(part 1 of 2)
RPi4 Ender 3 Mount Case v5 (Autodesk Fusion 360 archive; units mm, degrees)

design "RPi4 Ender 3 Mount Case" references "RPi_4_dummy_v2"
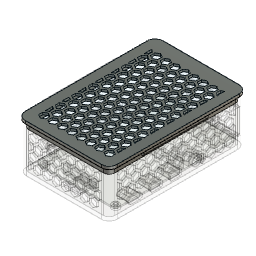
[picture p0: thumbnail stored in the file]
parameter "inner_width" = 60
parameter "inner_length" = 92
parameter "inner_height" = 30
parameter "wall_thickness" = 1.5
parameter "tolerance" = 0.2
parameter "cover_height" = 2
sketch "Sketch1" plane through (0, 0, 0) normal (0, 0, 1) x axis (1, 0, 0)
  line L1 (60, 0) -> (0, 0)
  line L2 (60, -92) -> (60, 0)
  line L3 (0, -92) -> (60, -92)
  line L4 (0, 0) -> (0, -92)
  point P1 (0, 0)
  point P2 (0, 0)
  point P3 (60, 0)
  point P5 (0, -92)
  horizontal L1
  vertical L2
  horizontal L3
  vertical L4
  coincident P1 P2
  dimension "d6" distance P2 P3 = 60 (= "inner_width")
  dimension "d7" distance P2 P5 = 92 (= "inner_length")
extrude "Extrude1" new body sketch "Sketch1" along normal blind 30 (= "inner_height")
fillet "Fillet1" radius 4
shell "Shell1" outerThickness 1.5 (= "wall_thickness")
sketch "Sketch2" plane through (0, 0, 0) normal (1, 0, 0) x axis (0, 1, 0)
  line L1 (-4, 30) -> (-4, 0)
  line L2 (-88, 30) -> (-4, 30)
  line L3 (-88, 0) -> (-88, 30)
  line L4 (-4, 0) -> (-88, 0)
  line L5 (-23, 28.5) -> (-69, 28.5)
  line L6 (-23, 26.25) -> (-23, 28.5)
  line L7 (-69, 26.25) -> (-23, 26.25)
  line L8 (-69, 28.5) -> (-69, 26.25)
  line L9 (-46, 30) -> (-46, 28.5)
  point P10 (-46, 28.5)
  point P11 (-46, 30)
  point P8 (-23, 26.25)
  point P9 (-69, 26.25)
  point P6 (-69, 28.5)
  horizontal L5
  vertical L6
  horizontal L7
  vertical L8
  midpoint L5 P10
  perpendicular L5 L9
  midpoint L2 P11
  dimension "d32" distance P8 P9 = 46 (= "inner_length / 2")
  dimension "d33" distance P6 P9 = 2.25 (= "wall_thickness * 1.5")
  dimension "d34" distance P10 P11 = 1.5 (= "wall_thickness")
extrude "Extrude2" cut sketch "Sketch2" profile of L5 L6 L7 L8 no distance stored taper -45
work_plane "WorkPlane1"
mirror "Mirror1" mirrorStitchTolerance 0.1
sketch "Sketch1" plane through (0, 0, 30) normal (0, 0, 1) x axis (-1, 0, 0)
  line L1 (-56, 0) -> (-4, 0)
  line L2 (-60, 88) -> (-60, 4)
  line L3 (-4, 92) -> (-56, 92)
  line L4 (0, 4) -> (0, 88)
  line L5 (-61.5, 4) -> (-61.5, 88)
  line L6 (-4, -1.5) -> (-56, -1.5)
  line L7 (1.5, 88) -> (1.5, 4)
  line L8 (-56, 93.5) -> (-4, 93.5)
  arc A1 centre (-4, 4) radius 4 clockwise from (0, 4) to (-4, 0)
  arc A2 centre (-56, 4) radius 4 clockwise from (-56, 0) to (-60, 4)
  arc A3 centre (-56, 88) radius 4 clockwise from (-60, 88) to (-56, 92)
  arc A4 centre (-4, 88) radius 4 clockwise from (-4, 92) to (0, 88)
  arc A5 centre (-56, 88) radius 5.5 clockwise from (-61.5, 88) to (-56, 93.5)
  arc A6 centre (-56, 4) radius 5.5 clockwise from (-56, -1.5) to (-61.5, 4)
  arc A7 centre (-4, 4) radius 5.5 clockwise from (1.5, 4) to (-4, -1.5)
  arc A8 centre (-4, 88) radius 5.5 clockwise from (-4, 93.5) to (1.5, 88)
extrude "Extrude1" new body sketch "Sketch1" along normal blind 2 (= "cover_height")
sketch "Sketch2" plane through (0, 0, 30) normal (0, 0, -1) x axis (1, 0, 0)
  line L1 (4, 93.5) -> (56, 93.5)
  line L2 (-1.5, 4) -> (-1.5, 88)
  line L3 (56, -1.5) -> (4, -1.5)
  line L4 (61.5, 88) -> (61.5, 4)
  line L5 (4, 91.8) -> (56, 91.8)
  line L6 (0.2, 4) -> (0.2, 88)
  line L7 (56, 0.2) -> (4, 0.2)
  line L8 (59.8, 88) -> (59.8, 4)
  arc A1 centre (4, 88) radius 5.5 clockwise from (-1.5, 88) to (4, 93.5)
  arc A2 centre (4, 4) radius 5.5 clockwise from (4, -1.5) to (-1.5, 4)
  arc A3 centre (56, 4) radius 5.5 clockwise from (61.5, 4) to (56, -1.5)
  arc A4 centre (56, 88) radius 5.5 clockwise from (56, 93.5) to (61.5, 88)
  arc A5 centre (4, 88) radius 3.8 clockwise from (0.2, 88) to (4, 91.8)
  arc A6 centre (4, 4) radius 3.8 clockwise from (4, 0.2) to (0.2, 4)
  arc A7 centre (56, 4) radius 3.8 clockwise from (59.8, 4) to (56, 0.2)
  arc A8 centre (56, 88) radius 3.8 clockwise from (56, 91.8) to (59.8, 88)
extrude "Extrude2" add sketch "Sketch2" profile of A8 L8 A7 A6 L6 L7 A5 L5 along normal blind 4.5 (= "wall_thickness * 3")
shell "Shell1" innerThickness 1.5 (= "wall_thickness")
sketch "Sketch3" plane through (0.2, 0, 0) normal (-1, 0, 0) x axis (0, -1, 0)
  line L1 (4, 30) -> (88, 30)
  line L2 (4, 25.5) -> (4, 30)
  line L3 (88, 25.5) -> (4, 25.5)
  line L4 (88, 30) -> (88, 25.5)
  line L5 (69, 26.25) -> (23, 26.25)
  line L6 (69, 28.5) -> (69, 26.25)
  line L7 (23, 26.25) -> (23, 28.5)
  line L8 (23, 28.5) -> (69, 28.5)
extrude "Extrude3" add sketch "Sketch3" profile of L5 L6 L7 L8 along normal blind 1.5 (= "wall_thickness") taper -45
mirror "Mirror1" mirrorStitchTolerance 0.1
offset_faces "OffsetFaces1" distance 0.5
chamfer "Chamfer1" distance 0.5
external_derived "ExternalDerived1" sketch "Sketch3" bodies "Body1", "Body2", "Power USB C", "Micro HDMI 2", "3.5 mm Audio", "Micro HDMI 1", "USB 2.0", "Display"
position "Position1"
sketch "Sketch1" plane through (0, 0, 0) normal (0, 0, 1) x axis (-1, 0, 0)
  line L1 (-60, 4) -> (-60, 88)
  line L2 (-4, 0) -> (-56, 0)
  line L3 (0, 88) -> (0, 4)
  line L4 (-56, 92) -> (-4, 92)
  arc A1 centre (-56, 88) radius 4 clockwise from (-60, 88) to (-56, 92)
  arc A2 centre (-56, 4) radius 4 clockwise from (-56, 0) to (-60, 4)
  arc A3 centre (-4, 4) radius 4 clockwise from (0, 4) to (-4, 0)
  arc A4 centre (-4, 88) radius 4 clockwise from (-4, 92) to (0, 88)
  circle C1 centre (-55.5, 24.9993) radius 1.35
  circle C2 centre (-6.5, 24.9993) radius 1.35
  circle C3 centre (-6.5, 82.9993) radius 1.35
  circle C4 centre (-55.5, 82.9993) radius 1.35
extrude "Extrude3" add sketch "Sketch1" profile of C1 C2 C3 C4 to an object
offset_faces "OffsetFaces1" distance 1.2
sketch "Sketch2" plane through (0, 1.5, 0) normal (0, 1, 0) x axis (-1, 0, 0)
  line L1 (-4, 30) -> (-4, -1.5)
  line L2 (-56, 30) -> (-4, 30)
  line L3 (-56, -1.5) -> (-56, 30)
  line L4 (-4, -1.5) -> (-56, -1.5)
  line L5 (-42.65, 3) -> (-57.35, 3)
  line L6 (-42.65, 19.5) -> (-42.65, 3)
  line L7 (-57.35, 19.5) -> (-42.65, 19.5)
  line L8 (-57.35, 3) -> (-57.35, 19.5)
  line L9 (-24.65, 3) -> (-39.35, 3)
  line L10 (-24.65, 19.5) -> (-24.65, 3)
  line L11 (-39.35, 19.5) -> (-24.65, 19.5)
  line L12 (-39.35, 3) -> (-39.35, 19.5)
  line L13 (-5.25, 3) -> (-21.25, 3)
  line L14 (-5.25, 16.5) -> (-5.25, 3)
  line L15 (-21.25, 16.5) -> (-5.25, 16.5)
  line L16 (-21.25, 3) -> (-21.25, 16.5)
  line L17 (-42.15, 2.5) -> (-57.85, 2.5)
  line L18 (-42.15, 20) -> (-42.15, 2.5)
  line L19 (-57.85, 20) -> (-42.15, 20)
  line L20 (-57.85, 2.5) -> (-57.85, 20)
  line L21 (-24.15, 2.5) -> (-39.85, 2.5)
  line L22 (-24.15, 20) -> (-24.15, 2.5)
  line L23 (-39.85, 20) -> (-24.15, 20)
  line L24 (-39.85, 2.5) -> (-39.85, 20)
  line L25 (-4.75, 2.5) -> (-21.75, 2.5)
  line L26 (-4.75, 17) -> (-4.75, 2.5)
  line L27 (-21.75, 17) -> (-4.75, 17)
  line L28 (-21.75, 2.5) -> (-21.75, 17)
  dimension "d44" = 0.5
  dimension "d45" = 0.5 (= "d44")
  dimension "d46" = 0.5 (= "d45")
extrude "Extrude5" cut sketch "Sketch2" profile of L1 L3 L19 L20 L18 L17 L23 L22 L24 L21 L28 L27 L26 L25 against normal blind 3 (magnitude of "-wall_thickness * 2")
sketch "Sketch3" plane through (61.5, 0, 0) normal (1, 0, 0) x axis (0, 1, 0)
  line L1 (-88, -1.5) -> (-88, 30)
  line L2 (-4, -1.5) -> (-88, -1.5)
  line L3 (-4, 30) -> (-4, -1.5)
  line L4 (-88, 30) -> (-4, 30)
  line L5 (-70.7993, 4.7) -> (-70.7993, 4.5)
  line L6 (-78.2993, 6.2) -> (-72.2993, 6.2)
  line L7 (-79.7993, 4.5) -> (-79.7993, 4.7)
  line L8 (-72.2993, 3) -> (-78.2993, 3)
  line L9 (-56.9493, 5.8) -> (-56.9493, 3.5)
  line L10 (-63.5493, 6.3) -> (-57.4493, 6.3)
  line L11 (-64.0493, 3.5) -> (-64.0493, 5.8)
  line L12 (-57.4493, 3) -> (-63.5493, 3)
  line L13 (-43.4493, 5.8) -> (-43.4493, 3.5)
  line L14 (-50.0493, 6.3) -> (-43.9493, 6.3)
  line L15 (-50.5493, 3.5) -> (-50.5493, 5.8)
  line L16 (-43.9493, 3) -> (-50.0493, 3)
  line L17 (-80.2993, 4.5) -> (-80.2993, 4.7)
  line L18 (-72.2993, 2.5) -> (-78.2993, 2.5)
  line L19 (-70.2993, 4.7) -> (-70.2993, 4.5)
  line L20 (-78.2993, 6.7) -> (-72.2993, 6.7)
  line L21 (-64.5493, 3.5) -> (-64.5493, 5.8)
  line L22 (-57.4493, 2.5) -> (-63.5493, 2.5)
  line L23 (-56.4493, 5.8) -> (-56.4493, 3.5)
  line L24 (-63.5493, 6.8) -> (-57.4493, 6.8)
  line L25 (-51.0493, 3.5) -> (-51.0493, 5.8)
  line L26 (-43.9493, 2.5) -> (-50.0493, 2.5)
  line L27 (-42.9493, 5.8) -> (-42.9493, 3.5)
  line L28 (-50.0493, 6.8) -> (-43.9493, 6.8)
  arc A1 centre (-72.2993, 4.5) radius 1.5 clockwise from (-70.7993, 4.5) to (-72.2993, 3)
  arc A2 centre (-72.2993, 4.7) radius 1.5 clockwise from (-72.2993, 6.2) to (-70.7993, 4.7)
  arc A3 centre (-78.2993, 4.7) radius 1.5 clockwise from (-79.7993, 4.7) to (-78.2993, 6.2)
  arc A4 centre (-78.2993, 4.5) radius 1.5 clockwise from (-78.2993, 3) to (-79.7993, 4.5)
  arc A5 centre (-57.4493, 3.5) radius 0.5 clockwise from (-56.9493, 3.5) to (-57.4493, 3)
  arc A6 centre (-57.4493, 5.8) radius 0.5 clockwise from (-57.4493, 6.3) to (-56.9493, 5.8)
  arc A7 centre (-63.5493, 5.8) radius 0.5 clockwise from (-64.0493, 5.8) to (-63.5493, 6.3)
  arc A8 centre (-63.5493, 3.5) radius 0.5 clockwise from (-63.5493, 3) to (-64.0493, 3.5)
  arc A9 centre (-43.9493, 3.5) radius 0.5 clockwise from (-43.4493, 3.5) to (-43.9493, 3)
  arc A10 centre (-43.9493, 5.8) radius 0.5 clockwise from (-43.9493, 6.3) to (-43.4493, 5.8)
  arc A11 centre (-50.0493, 5.8) radius 0.5 clockwise from (-50.5493, 5.8) to (-50.0493, 6.3)
  arc A12 centre (-50.0493, 3.5) radius 0.5 clockwise from (-50.0493, 3) to (-50.5493, 3.5)
  circle C1 centre (-32.4993, 6) radius 3
  arc A13 centre (-78.2993, 4.5) radius 2 clockwise from (-78.2993, 2.5) to (-80.2993, 4.5)
  arc A14 centre (-72.2993, 4.5) radius 2 clockwise from (-70.2993, 4.5) to (-72.2993, 2.5)
  arc A15 centre (-72.2993, 4.7) radius 2 clockwise from (-72.2993, 6.7) to (-70.2993, 4.7)
  arc A16 centre (-78.2993, 4.7) radius 2 clockwise from (-80.2993, 4.7) to (-78.2993, 6.7)
  arc A17 centre (-63.5493, 3.5) radius 1 clockwise from (-63.5493, 2.5) to (-64.5493, 3.5)
  arc A18 centre (-57.4493, 3.5) radius 1 clockwise from (-56.4493, 3.5) to (-57.4493, 2.5)
  arc A19 centre (-57.4493, 5.8) radius 1 clockwise from (-57.4493, 6.8) to (-56.4493, 5.8)
  arc A20 centre (-63.5493, 5.8) radius 1 clockwise from (-64.5493, 5.8) to (-63.5493, 6.8)
  arc A21 centre (-50.0493, 3.5) radius 1 clockwise from (-50.0493, 2.5) to (-51.0493, 3.5)
  arc A22 centre (-43.9493, 3.5) radius 1 clockwise from (-42.9493, 3.5) to (-43.9493, 2.5)
  arc A23 centre (-43.9493, 5.8) radius 1 clockwise from (-43.9493, 6.8) to (-42.9493, 5.8)
  arc A24 centre (-50.0493, 5.8) radius 1 clockwise from (-51.0493, 5.8) to (-50.0493, 6.8)
  circle C2 centre (-32.4993, 6) radius 3.5
  dimension "d49" = 0.5
  dimension "d50" = 0.5
  dimension "d51" = 0.5
  dimension "d52" = 0.5
extrude "Extrude6" cut sketch "Sketch3" profile of A16 L20 A15 L19 L18 A14 A13 L17 L24 A20 A19 L23 L22 A18 A17 L21 L28 A23 A24 L27 L26 A22 A21 L25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 against normal blind 3 (magnitude of "-wall_thickness * 2")
sketch "Sketch5" plane through (61.5, 0, 0) normal (1, 0, 0) x axis (0, 1, 0)
  line L1 (-64.5493, 5.8) -> (-64.5493, 3.5)
  line L2 (-57.4493, 6.8) -> (-63.5493, 6.8)
  line L3 (-56.4493, 3.5) -> (-56.4493, 5.8)
  line L4 (-63.5493, 2.5) -> (-57.4493, 2.5)
  line L5 (-51.0493, 5.8) -> (-51.0493, 3.5)
  line L6 (-43.9493, 6.8) -> (-50.0493, 6.8)
  line L7 (-42.9493, 3.5) -> (-42.9493, 5.8)
  line L8 (-50.0493, 2.5) -> (-43.9493, 2.5)
  line L9 (-80.2993, 4.7) -> (-80.2993, 4.5)
  line L10 (-72.2993, 6.7) -> (-78.2993, 6.7)
  line L11 (-70.2993, 4.5) -> (-70.2993, 4.7)
  line L12 (-78.2993, 2.5) -> (-72.2993, 2.5)
  line L13 (-88, -1.5) -> (-88, 30)
  line L14 (-4, -1.5) -> (-88, -1.5)
  line L15 (-4, 30) -> (-4, -1.5)
  line L16 (-88, 30) -> (-4, 30)
  line L17 (-5.5, 0) -> (-86.5, 0)
  line L18 (-5.5, 28.5) -> (-5.5, 0)
  line L19 (-86.5, 28.5) -> (-5.5, 28.5)
  line L20 (-86.5, 0) -> (-86.5, 28.5)
  line L21 (-72.2993, 8.2) -> (-78.2993, 8.2)
  line L22 (-68.7993, 4.5) -> (-68.7993, 4.7)
  line L23 (-78.2993, 1) -> (-72.2993, 1)
  line L24 (-81.7993, 4.7) -> (-81.7993, 4.5)
  line L25 (-54.9493, 3.5) -> (-54.9493, 5.8)
  line L26 (-57.4493, 8.3) -> (-63.5493, 8.3)
  line L27 (-66.0493, 5.8) -> (-66.0493, 3.5)
  line L28 (-63.5493, 1) -> (-57.4493, 1)
  line L29 (-41.4493, 3.5) -> (-41.4493, 5.8)
  line L30 (-43.9493, 8.3) -> (-50.0493, 8.3)
  line L31 (-52.5493, 5.8) -> (-52.5493, 3.5)
  line L32 (-50.0493, 1) -> (-43.9493, 1)
  line L33 (-87.25, 19.6699) -> (-84.75, 18.2265)
  line L34 (-89.75, 18.2265) -> (-87.25, 19.6699)
  line L35 (-89.75, 15.3397) -> (-89.75, 18.2265)
  line L36 (-87.25, 13.8964) -> (-89.75, 15.3397)
  line L37 (-84.75, 15.3397) -> (-87.25, 13.8964)
  line L38 (-84.75, 18.2265) -> (-84.75, 15.3397)
  line L39 (-84, 25.5) -> (-81.5, 24.0566)
  line L40 (-86.5, 24.0566) -> (-84, 25.5)
  line L41 (-86.5, 21.1699) -> (-86.5, 24.0566)
  line L42 (-84, 19.7265) -> (-86.5, 21.1699)
  line L43 (-81.5, 21.1699) -> (-84, 19.7265)
  line L44 (-81.5, 24.0566) -> (-81.5, 21.1699)
  line L45 (-77.5, 25.5) -> (-75, 24.0566)
  line L46 (-80, 24.0566) -> (-77.5, 25.5)
  line L47 (-80, 21.1699) -> (-80, 24.0566)
  line L48 (-77.5, 19.7265) -> (-80, 21.1699)
  line L49 (-75, 21.1699) -> (-77.5, 19.7265)
  line L50 (-75, 24.0566) -> (-75, 21.1699)
  line L51 (-80.75, 19.6699) -> (-78.25, 18.2265)
  line L52 (-83.25, 18.2265) -> (-80.75, 19.6699)
  line L53 (-83.25, 15.3397) -> (-83.25, 18.2265)
  line L54 (-80.75, 13.8964) -> (-83.25, 15.3397)
  line L55 (-78.25, 18.2265) -> (-78.25, 15.3397)
  line L56 (-78.25, 15.3397) -> (-80.75, 13.8964)
  line L57 (-71, 25.5) -> (-68.5, 24.0566)
  line L58 (-73.5, 24.0566) -> (-71, 25.5)
  line L59 (-73.5, 21.1699) -> (-73.5, 24.0566)
  line L60 (-71, 19.7265) -> (-73.5, 21.1699)
  line L61 (-68.5, 21.1699) -> (-71, 19.7265)
  line L62 (-68.5, 24.0566) -> (-68.5, 21.1699)
  line L63 (-74.25, 19.6699) -> (-71.75, 18.2265)
  line L64 (-76.75, 18.2265) -> (-74.25, 19.6699)
  line L65 (-76.75, 15.3397) -> (-76.75, 18.2265)
  line L66 (-74.25, 13.8964) -> (-76.75, 15.3397)
  line L67 (-71.75, 18.2265) -> (-71.75, 15.3397)
  line L68 (-71.75, 15.3397) -> (-74.25, 13.8964)
  line L69 (-64.5, 25.5) -> (-62, 24.0566)
  line L70 (-67, 24.0566) -> (-64.5, 25.5)
  line L71 (-67, 21.1699) -> (-67, 24.0566)
  line L72 (-64.5, 19.7265) -> (-67, 21.1699)
  line L73 (-62, 21.1699) -> (-64.5, 19.7265)
  line L74 (-62, 24.0566) -> (-62, 21.1699)
  line L75 (-67.75, 19.6699) -> (-65.25, 18.2265)
  line L76 (-70.25, 18.2265) -> (-67.75, 19.6699)
  line L77 (-70.25, 15.3397) -> (-70.25, 18.2265)
  line L78 (-67.75, 13.8964) -> (-70.25, 15.3397)
  line L79 (-65.25, 18.2265) -> (-65.25, 15.3397)
  line L80 (-65.25, 15.3397) -> (-67.75, 13.8964)
  line L81 (-58, 25.5) -> (-55.5, 24.0566)
  line L82 (-60.5, 24.0566) -> (-58, 25.5)
  line L83 (-60.5, 21.1699) -> (-60.5, 24.0566)
  line L84 (-58, 19.7265) -> (-60.5, 21.1699)
  line L85 (-55.5, 21.1699) -> (-58, 19.7265)
  line L86 (-55.5, 24.0566) -> (-55.5, 21.1699)
  line L87 (-61.25, 19.6699) -> (-58.75, 18.2265)
  line L88 (-63.75, 18.2265) -> (-61.25, 19.6699)
  line L89 (-63.75, 15.3397) -> (-63.75, 18.2265)
  line L90 (-61.25, 13.8964) -> (-63.75, 15.3397)
  line L91 (-58.75, 18.2265) -> (-58.75, 15.3397)
  line L92 (-58.75, 15.3397) -> (-61.25, 13.8964)
  line L93 (-51.5, 25.5) -> (-49, 24.0566)
  line L94 (-54, 24.0566) -> (-51.5, 25.5)
  line L95 (-54, 21.1699) -> (-54, 24.0566)
  line L96 (-51.5, 19.7265) -> (-54, 21.1699)
  line L97 (-49, 21.1699) -> (-51.5, 19.7265)
  line L98 (-49, 24.0566) -> (-49, 21.1699)
  line L99 (-54.75, 19.6699) -> (-52.25, 18.2265)
  line L100 (-57.25, 18.2265) -> (-54.75, 19.6699)
  line L101 (-57.25, 15.3397) -> (-57.25, 18.2265)
  line L102 (-54.75, 13.8964) -> (-57.25, 15.3397)
  line L103 (-52.25, 18.2265) -> (-52.25, 15.3397)
  line L104 (-52.25, 15.3397) -> (-54.75, 13.8964)
  line L105 (-45, 25.5) -> (-42.5, 24.0566)
  line L106 (-47.5, 24.0566) -> (-45, 25.5)
  line L107 (-47.5, 21.1699) -> (-47.5, 24.0566)
  line L108 (-45, 19.7265) -> (-47.5, 21.1699)
  line L109 (-42.5, 21.1699) -> (-45, 19.7265)
  line L110 (-42.5, 24.0566) -> (-42.5, 21.1699)
  line L111 (-48.25, 19.6699) -> (-45.75, 18.2265)
  line L112 (-50.75, 18.2265) -> (-48.25, 19.6699)
  line L113 (-50.75, 15.3397) -> (-50.75, 18.2265)
  line L114 (-48.25, 13.8964) -> (-50.75, 15.3397)
  line L115 (-45.75, 18.2265) -> (-45.75, 15.3397)
  line L116 (-45.75, 15.3397) -> (-48.25, 13.8964)
  line L117 (-38.5, 25.5) -> (-36, 24.0566)
  line L118 (-41, 24.0566) -> (-38.5, 25.5)
  line L119 (-41, 21.1699) -> (-41, 24.0566)
  line L120 (-38.5, 19.7265) -> (-41, 21.1699)
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  point P90 (-87.25, 16.7831)
  point P97 (-84, 22.6132)
  point P85 (-87.25, 19.6699)
  point P94 (-86.5, 21.1699)
  point P92 (-84, 25.5)
  vertical L38
  vertical L44
  collinear L20 L41
  dimension "d81" = 1.5 (= "wall_thickness")
  dimension "d84" = 1.5 (= "wall_thickness")
  dimension "d85" distance P90 L38 = 2.5
  dimension "d86" distance P97 L44 = 2.5
  dimension "d87" distance P85 P94 = 1.5 (= "wall_thickness")
  dimension "d88" distance L20 P85 = 0.75 (= "wall_thickness / 2")
  dimension "d95" distance L19 P92 = 3
  dimension "d91" R-Pattern1-uDistance = 6.5
  dimension "d92" R-Pattern1-vDistance = -11.5
extrude "Extrude9" cut sketch "Sketch5" no distance stored
sketch "Sketch6" plane through (0, -93.5, 0) normal (0, -1, 0) x axis (1, 0, 0)
  line L1 (56, 30) -> (56, -1.5)
  line L2 (4, 30) -> (56, 30)
  line L3 (4, -1.5) -> (4, 30)
  line L4 (56, -1.5) -> (4, -1.5)
  line L5 (54.5, 0) -> (5.5, 0)
  line L6 (54.5, 28.5) -> (54.5, 0)
  line L7 (5.5, 28.5) -> (54.5, 28.5)
  line L8 (5.5, 0) -> (5.5, 28.5)
  line L9 (8, 25.5) -> (10.5, 24.0566)
  line L10 (5.5, 24.0566) -> (8, 25.5)
  line L11 (5.5, 21.1699) -> (5.5, 24.0566)
  line L12 (8, 19.7265) -> (5.5, 21.1699)
  line L13 (10.5, 21.1699) -> (8, 19.7265)
  line L14 (10.5, 24.0566) -> (10.5, 21.1699)
  line L15 (4.75, 19.6699) -> (7.25, 18.2265)
  line L16 (2.25, 18.2265) -> (4.75, 19.6699)
  line L17 (2.25, 15.3397) -> (2.25, 18.2265)
  line L18 (4.75, 13.8964) -> (2.25, 15.3397)
  line L19 (7.25, 15.3397) -> (4.75, 13.8964)
  line L20 (7.25, 18.2265) -> (7.25, 15.3397)
  line L21 (14.5, 25.5) -> (17, 24.0566)
  line L22 (12, 24.0566) -> (14.5, 25.5)
  line L23 (12, 21.1699) -> (12, 24.0566)
  line L24 (14.5, 19.7265) -> (12, 21.1699)
  line L25 (17, 21.1699) -> (14.5, 19.7265)
  line L26 (17, 24.0566) -> (17, 21.1699)
  line L27 (11.25, 19.6699) -> (13.75, 18.2265)
  line L28 (8.75, 18.2265) -> (11.25, 19.6699)
  line L29 (8.75, 15.3397) -> (8.75, 18.2265)
  line L30 (11.25, 13.8964) -> (8.75, 15.3397)
  line L31 (13.75, 18.2265) -> (13.75, 15.3397)
  line L32 (13.75, 15.3397) -> (11.25, 13.8964)
  line L33 (21, 25.5) -> (23.5, 24.0566)
  line L34 (18.5, 24.0566) -> (21, 25.5)
  line L35 (18.5, 21.1699) -> (18.5, 24.0566)
  line L36 (21, 19.7265) -> (18.5, 21.1699)
  line L37 (23.5, 21.1699) -> (21, 19.7265)
  line L38 (23.5, 24.0566) -> (23.5, 21.1699)
  line L39 (17.75, 19.6699) -> (20.25, 18.2265)
  line L40 (15.25, 18.2265) -> (17.75, 19.6699)
  line L41 (15.25, 15.3397) -> (15.25, 18.2265)
  line L42 (17.75, 13.8964) -> (15.25, 15.3397)
  line L43 (20.25, 18.2265) -> (20.25, 15.3397)
  line L44 (20.25, 15.3397) -> (17.75, 13.8964)
  line L45 (27.5, 25.5) -> (30, 24.0566)
  line L46 (25, 24.0566) -> (27.5, 25.5)
  line L47 (25, 21.1699) -> (25, 24.0566)
  line L48 (27.5, 19.7265) -> (25, 21.1699)
  line L49 (30, 21.1699) -> (27.5, 19.7265)
  line L50 (30, 24.0566) -> (30, 21.1699)
  line L51 (24.25, 19.6699) -> (26.75, 18.2265)
  line L52 (21.75, 18.2265) -> (24.25, 19.6699)
  line L53 (21.75, 15.3397) -> (21.75, 18.2265)
  line L54 (24.25, 13.8964) -> (21.75, 15.3397)
  line L55 (26.75, 18.2265) -> (26.75, 15.3397)
  line L56 (26.75, 15.3397) -> (24.25, 13.8964)
  line L57 (34, 25.5) -> (36.5, 24.0566)
  line L58 (31.5, 24.0566) -> (34, 25.5)
  line L59 (31.5, 21.1699) -> (31.5, 24.0566)
  line L60 (34, 19.7265) -> (31.5, 21.1699)
  line L61 (36.5, 21.1699) -> (34, 19.7265)
  line L62 (36.5, 24.0566) -> (36.5, 21.1699)
  line L63 (30.75, 19.6699) -> (33.25, 18.2265)
  line L64 (28.25, 18.2265) -> (30.75, 19.6699)
  line L65 (28.25, 15.3397) -> (28.25, 18.2265)
  line L66 (30.75, 13.8964) -> (28.25, 15.3397)
  line L67 (33.25, 18.2265) -> (33.25, 15.3397)
  line L68 (33.25, 15.3397) -> (30.75, 13.8964)
  line L69 (40.5, 25.5) -> (43, 24.0566)
  line L70 (38, 24.0566) -> (40.5, 25.5)
  line L71 (38, 21.1699) -> (38, 24.0566)
  line L72 (40.5, 19.7265) -> (38, 21.1699)
  line L73 (43, 21.1699) -> (40.5, 19.7265)
  line L74 (43, 24.0566) -> (43, 21.1699)
  line L75 (37.25, 19.6699) -> (39.75, 18.2265)
  line L76 (34.75, 18.2265) -> (37.25, 19.6699)
  line L77 (34.75, 15.3397) -> (34.75, 18.2265)
  line L78 (37.25, 13.8964) -> (34.75, 15.3397)
  line L79 (39.75, 18.2265) -> (39.75, 15.3397)
  line L80 (39.75, 15.3397) -> (37.25, 13.8964)
  line L81 (47, 25.5) -> (49.5, 24.0566)
  line L82 (44.5, 24.0566) -> (47, 25.5)
  line L83 (44.5, 21.1699) -> (44.5, 24.0566)
  line L84 (47, 19.7265) -> (44.5, 21.1699)
  line L85 (49.5, 21.1699) -> (47, 19.7265)
  line L86 (49.5, 24.0566) -> (49.5, 21.1699)
  line L87 (43.75, 19.6699) -> (46.25, 18.2265)
  line L88 (41.25, 18.2265) -> (43.75, 19.6699)
  line L89 (41.25, 15.3397) -> (41.25, 18.2265)
  line L90 (43.75, 13.8964) -> (41.25, 15.3397)
  line L91 (46.25, 18.2265) -> (46.25, 15.3397)
  line L92 (46.25, 15.3397) -> (43.75, 13.8964)
  line L93 (53.5, 25.5) -> (56, 24.0566)
  line L94 (51, 24.0566) -> (53.5, 25.5)
  line L95 (51, 21.1699) -> (51, 24.0566)
  line L96 (53.5, 19.7265) -> (51, 21.1699)
  line L97 (56, 21.1699) -> (53.5, 19.7265)
  line L98 (56, 24.0566) -> (56, 21.1699)
  line L99 (50.25, 19.6699) -> (52.75, 18.2265)
  line L100 (47.75, 18.2265) -> (50.25, 19.6699)
  line L101 (47.75, 15.3397) -> (47.75, 18.2265)
  line L102 (50.25, 13.8964) -> (47.75, 15.3397)
  line L103 (52.75, 18.2265) -> (52.75, 15.3397)
  line L104 (52.75, 15.3397) -> (50.25, 13.8964)
  line L105 (8, 14) -> (10.5, 12.5566)
  line L106 (5.5, 12.5566) -> (8, 14)
  line L107 (5.5, 9.6699) -> (5.5, 12.5566)
  line L108 (8, 8.2265) -> (5.5, 9.6699)
  line L109 (10.5, 9.6699) -> (8, 8.2265)
  line L110 (10.5, 12.5566) -> (10.5, 9.6699)
  line L111 (4.75, 8.1699) -> (7.25, 6.7265)
  line L112 (2.25, 6.7265) -> (4.75, 8.1699)
  line L113 (2.25, 3.8397) -> (2.25, 6.7265)
  line L114 (4.75, 2.3964) -> (2.25, 3.8397)
  line L115 (7.25, 6.7265) -> (7.25, 3.8397)
  line L116 (7.25, 3.8397) -> (4.75, 2.3964)
  line L117 (14.5, 14) -> (17, 12.5566)
  line L118 (12, 12.5566) -> (14.5, 14)
  line L119 (12, 9.6699) -> (12, 12.5566)
  line L120 (14.5, 8.2265) -> (12, 9.6699)
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  point P16 (8, 22.6132)
  point P11 (8, 25.5)
  point P23 (4.75, 16.7831)
  point P18 (4.75, 19.6699)
  point P13 (5.5, 21.1699)
  vertical L14
  collinear L8 L11
  vertical L20
  dimension "d99" distance P16 L14 = 2.5
  dimension "d100" distance L7 P11 = 3
  dimension "d101" distance P23 L20 = 2.5
  dimension "d102" distance L8 P18 = 0.75 (= "wall_thickness / 2")
  dimension "d103" distance P13 P18 = 1.5 (= "wall_thickness")
  dimension "d106" R-Pattern1-uDistance = 6.5 (= "( 2.5 * 2 ) * 1 mm + wall_thickness")
  dimension "d107" R-Pattern1-vDistance = -11.5 (= "-( ( 2.5 * 4 ) * 1 mm + wall_thickness )")
extrude "Extrude10" cut sketch "Sketch6" no distance stored
sketch "Sketch4" plane through (0, 0, 30.5) normal (0, 0, -1) x axis (1, 0, 0)
  line L1 (4, 90.3) -> (56, 90.3)
  line L2 (1.7, 4) -> (1.7, 88)
  line L3 (56, 1.7) -> (4, 1.7)
  line L4 (58.3, 88) -> (58.3, 4)
  line L5 (4.7, 4.7) -> (4.7, 87.3)
  line L6 (55.3, 4.7) -> (4.7, 4.7)
  line L7 (55.3, 87.3) -> (55.3, 4.7)
  line L8 (4.7, 87.3) -> (55.3, 87.3)
  line L9 (7.2, 87.3) -> (9.7, 85.8566)
  line L10 (4.7, 85.8566) -> (7.2, 87.3)
  line L11 (4.7, 82.9699) -> (4.7, 85.8566)
  line L12 (7.2, 81.5265) -> (4.7, 82.9699)
  line L13 (9.7, 82.9699) -> (7.2, 81.5265)
  line L14 (9.7, 85.8566) -> (9.7, 82.9699)
  line L15 (3.95, 81.4699) -> (6.45, 80.0265)
  line L16 (1.45, 80.0265) -> (3.95, 81.4699)
  line L17 (1.45, 77.1397) -> (1.45, 80.0265)
  line L18 (3.95, 75.6964) -> (1.45, 77.1397)
  line L19 (6.45, 77.1397) -> (3.95, 75.6964)
  line L20 (6.45, 80.0265) -> (6.45, 77.1397)
  line L21 (13.7, 87.3) -> (16.2, 85.8566)
  line L22 (11.2, 85.8566) -> (13.7, 87.3)
  line L23 (11.2, 82.9699) -> (11.2, 85.8566)
  line L24 (13.7, 81.5265) -> (11.2, 82.9699)
  line L25 (16.2, 85.8566) -> (16.2, 82.9699)
  line L26 (16.2, 82.9699) -> (13.7, 81.5265)
  line L27 (12.95, 80.0265) -> (12.95, 77.1397)
  line L28 (10.45, 81.4699) -> (12.95, 80.0265)
  line L29 (7.95, 80.0265) -> (10.45, 81.4699)
  line L30 (7.95, 77.1397) -> (7.95, 80.0265)
  line L31 (12.95, 77.1397) -> (10.45, 75.6964)
  line L32 (10.45, 75.6964) -> (7.95, 77.1397)
  line L33 (20.2, 87.3) -> (22.7, 85.8566)
  line L34 (17.7, 85.8566) -> (20.2, 87.3)
  line L35 (17.7, 82.9699) -> (17.7, 85.8566)
  line L36 (20.2, 81.5265) -> (17.7, 82.9699)
  line L37 (22.7, 85.8566) -> (22.7, 82.9699)
  line L38 (22.7, 82.9699) -> (20.2, 81.5265)
  line L39 (19.45, 80.0265) -> (19.45, 77.1397)
  line L40 (16.95, 81.4699) -> (19.45, 80.0265)
  line L41 (14.45, 80.0265) -> (16.95, 81.4699)
  line L42 (14.45, 77.1397) -> (14.45, 80.0265)
  line L43 (19.45, 77.1397) -> (16.95, 75.6964)
  line L44 (16.95, 75.6964) -> (14.45, 77.1397)
  line L45 (7.2, 75.8) -> (9.7, 74.3566)
  line L46 (4.7, 74.3566) -> (7.2, 75.8)
  line L47 (4.7, 71.4699) -> (4.7, 74.3566)
  line L48 (7.2, 70.0265) -> (4.7, 71.4699)
  line L49 (9.7, 74.3566) -> (9.7, 71.4699)
  line L50 (9.7, 71.4699) -> (7.2, 70.0265)
  line L51 (6.45, 68.5265) -> (6.45, 65.6397)
  line L52 (3.95, 69.9699) -> (6.45, 68.5265)
  line L53 (1.45, 68.5265) -> (3.95, 69.9699)
  line L54 (1.45, 65.6397) -> (1.45, 68.5265)
  line L55 (6.45, 65.6397) -> (3.95, 64.1964)
  line L56 (3.95, 64.1964) -> (1.45, 65.6397)
  line L57 (13.7, 75.8) -> (16.2, 74.3566)
  line L58 (11.2, 74.3566) -> (13.7, 75.8)
  line L59 (11.2, 71.4699) -> (11.2, 74.3566)
  line L60 (13.7, 70.0265) -> (11.2, 71.4699)
  line L61 (16.2, 74.3566) -> (16.2, 71.4699)
  line L62 (16.2, 71.4699) -> (13.7, 70.0265)
  line L63 (12.95, 68.5265) -> (12.95, 65.6397)
  line L64 (10.45, 69.9699) -> (12.95, 68.5265)
  line L65 (7.95, 68.5265) -> (10.45, 69.9699)
  line L66 (7.95, 65.6397) -> (7.95, 68.5265)
  line L67 (12.95, 65.6397) -> (10.45, 64.1964)
  line L68 (10.45, 64.1964) -> (7.95, 65.6397)
  line L69 (20.2, 75.8) -> (22.7, 74.3566)
  line L70 (17.7, 74.3566) -> (20.2, 75.8)
  line L71 (17.7, 71.4699) -> (17.7, 74.3566)
  line L72 (20.2, 70.0265) -> (17.7, 71.4699)
  line L73 (22.7, 74.3566) -> (22.7, 71.4699)
  line L74 (22.7, 71.4699) -> (20.2, 70.0265)
  line L75 (19.45, 68.5265) -> (19.45, 65.6397)
  line L76 (16.95, 69.9699) -> (19.45, 68.5265)
  line L77 (14.45, 68.5265) -> (16.95, 69.9699)
  line L78 (14.45, 65.6397) -> (14.45, 68.5265)
  line L79 (19.45, 65.6397) -> (16.95, 64.1964)
  line L80 (16.95, 64.1964) -> (14.45, 65.6397)
  line L81 (7.2, 64.3) -> (9.7, 62.8566)
  line L82 (4.7, 62.8566) -> (7.2, 64.3)
  line L83 (4.7, 59.9699) -> (4.7, 62.8566)
  line L84 (7.2, 58.5265) -> (4.7, 59.9699)
  line L85 (9.7, 62.8566) -> (9.7, 59.9699)
  line L86 (9.7, 59.9699) -> (7.2, 58.5265)
  line L87 (6.45, 57.0265) -> (6.45, 54.1397)
  line L88 (3.95, 58.4699) -> (6.45, 57.0265)
  line L89 (1.45, 57.0265) -> (3.95, 58.4699)
  line L90 (1.45, 54.1397) -> (1.45, 57.0265)
  line L91 (6.45, 54.1397) -> (3.95, 52.6964)
  line L92 (3.95, 52.6964) -> (1.45, 54.1397)
  line L93 (13.7, 64.3) -> (16.2, 62.8566)
  line L94 (11.2, 62.8566) -> (13.7, 64.3)
  line L95 (11.2, 59.9699) -> (11.2, 62.8566)
  line L96 (13.7, 58.5265) -> (11.2, 59.9699)
  line L97 (16.2, 62.8566) -> (16.2, 59.9699)
  line L98 (16.2, 59.9699) -> (13.7, 58.5265)
  line L99 (12.95, 57.0265) -> (12.95, 54.1397)
  line L100 (10.45, 58.4699) -> (12.95, 57.0265)
  line L101 (7.95, 57.0265) -> (10.45, 58.4699)
  line L102 (7.95, 54.1397) -> (7.95, 57.0265)
  line L103 (12.95, 54.1397) -> (10.45, 52.6964)
  line L104 (10.45, 52.6964) -> (7.95, 54.1397)
  line L105 (20.2, 64.3) -> (22.7, 62.8566)
  line L106 (17.7, 62.8566) -> (20.2, 64.3)
  line L107 (17.7, 59.9699) -> (17.7, 62.8566)
  line L108 (20.2, 58.5265) -> (17.7, 59.9699)
  line L109 (22.7, 62.8566) -> (22.7, 59.9699)
  line L110 (22.7, 59.9699) -> (20.2, 58.5265)
  line L111 (19.45, 57.0265) -> (19.45, 54.1397)
  line L112 (16.95, 58.4699) -> (19.45, 57.0265)
  line L113 (14.45, 57.0265) -> (16.95, 58.4699)
  line L114 (14.45, 54.1397) -> (14.45, 57.0265)
  line L115 (19.45, 54.1397) -> (16.95, 52.6964)
  line L116 (16.95, 52.6964) -> (14.45, 54.1397)
  line L117 (26.7, 87.3) -> (29.2, 85.8566)
  line L118 (24.2, 85.8566) -> (26.7, 87.3)
  line L119 (24.2, 82.9699) -> (24.2, 85.8566)
  line L120 (26.7, 81.5265) -> (24.2, 82.9699)
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  point P19 (7.2, 87.3)
  point P20 (4.7, 85.8566)
  point P24 (7.2, 84.4132)
  point P31 (3.95, 78.5831)
  point P26 (3.95, 81.4699)
  point P21 (4.7, 82.9699)
  vertical L14
  vertical L20
  coincident L8 P19
  coincident L5 P20
  dimension "d110" = -3
  dimension "d111" distance P24 L14 = 2.5
  dimension "d112" distance P31 L20 = 2.5
  dimension "d113" distance L5 P26 = 0.75 (= "wall_thickness / 2")
  dimension "d114" distance P21 P26 = 1.5 (= "wall_thickness")
  dimension "d117" R-Pattern1-uDistance = 6.5 (= "5 mm + wall_thickness")
  dimension "d118" R-Pattern1-vDistance = -11.5 (= "-( 10 mm + wall_thickness )")
extrude "Extrude4" cut sketch "Sketch4" no distance stored
sketch "Sketch7" plane through (0, 1.5, 0) normal (0, 1, 0) x axis (-1, 0, 0)
  line L1 (-56, 2.5) -> (-42.15, 2.5)
  line L2 (-56, -1.5) -> (-56, 2.5)
  line L3 (-4, -1.5) -> (-56, -1.5)
  line L4 (-4, 30) -> (-4, -1.5)
  line L5 (-56, 30) -> (-4, 30)
  line L6 (-56, 20) -> (-56, 30)
  line L7 (-42.15, 20) -> (-56, 20)
  line L8 (-42.15, 2.5) -> (-42.15, 20)
  line L9 (-39.85, 2.5) -> (-24.15, 2.5)
  line L10 (-39.85, 20) -> (-39.85, 2.5)
  line L11 (-24.15, 20) -> (-39.85, 20)
  line L12 (-24.15, 2.5) -> (-24.15, 20)
  line L13 (-21.75, 2.5) -> (-4.75, 2.5)
  line L14 (-21.75, 17) -> (-21.75, 2.5)
  line L15 (-4.75, 17) -> (-21.75, 17)
  line L16 (-4.75, 2.5) -> (-4.75, 17)
  line L17 (1.5, 30) -> (1.5, -1.5)
  line L18 (17.1332, 14.25) -> (1.5, 14.25)
  line L19 (17.6053, 24.25) -> (1.5, 24.25)
  line L20 (3.3, 26.75) -> (1.5, 26.75)
  line L21 (3.3, 21.75) -> (3.3, 26.75)
  line L22 (1.5, 21.75) -> (3.3, 21.75)
  line L23 (1.5, 26.75) -> (1.5, 21.75)
  line L24 (4.6, 29.75) -> (3.3, 29.75)
  line L25 (7.8, 21.95) -> (7.8, 26.55)
  line L26 (3.3, 18.75) -> (4.6, 18.75)
  line L27 (3.3, 29.75) -> (3.3, 18.75)
  line L28 (4.6, 18.75) -> (4.6, 29.75)
  line L29 (7.8, 21.95) -> (4.6, 18.75)
  line L30 (9.7192, 18.45) -> (7.8, 18.45)
  line L31 (7.8, 26.55) -> (4.6, 29.75)
  line L32 (9.4083, 30.05) -> (7.8, 30.05)
  line L33 (7.8, 1.95) -> (4.6, -1.25)
  line L34 (7.8, 6.55) -> (7.8, 1.95)
  line L35 (7.8, 6.55) -> (4.6, 9.75)
  line L36 (3.3, 9.75) -> (4.6, 9.75)
  line L37 (4.6, -1.25) -> (3.3, -1.25)
  line L38 (3.3, -1.25) -> (3.3, 9.75)
  line L39 (4.6, 9.75) -> (4.6, -1.25)
  line L40 (1.5, 6.75) -> (3.3, 6.75)
  line L41 (1.5, 1.75) -> (1.5, 6.75)
  line L42 (3.3, 6.75) -> (3.3, 1.75)
  line L43 (3.3, 1.75) -> (1.5, 1.75)
  point P20 (1.5, 14.25)
  point P22 (1.5, 24.25)
  point P32 (3.3, 24.25)
  point P24 (1.5, 26.75)
  point P47 (1.5, 1.75)
  point P25 (3.3, 26.75)
  point P48 (3.3, 1.75)
  point P26 (3.3, 21.75)
  point P45 (3.3, 6.75)
  point P27 (1.5, 21.75)
  point P46 (1.5, 6.75)
  point P28 (3.3, 29.75)
  point P44 (3.3, -1.25)
  point P31 (3.3, 18.75)
  point P43 (3.3, 9.75)
  point P33 (4.6, 29.75)
  point P39 (4.6, -1.25)
  point P34 (4.6, 18.75)
  point P42 (4.6, 9.75)
  point P35 (7.8, 21.95)
  point P41 (7.8, 6.55)
  point P37 (7.8, 26.55)
  point P40 (7.8, 1.95)
  midpoint L17 P20
  perpendicular L17 L18
  coincident L17 P22
  perpendicular L17 L19
  horizontal L20
  vertical L21
  horizontal L22
  vertical L23
  midpoint P22 L23
  horizontal L24
  vertical L25
  horizontal L26
  vertical L27
  midpoint L21 P32
  midpoint L27 P32
  perpendicular L26 L28
  horizontal L30
  horizontal L32
  symmetric L18 P24 P47
  symmetric L18 P25 P48
  symmetric L18 P26 P45
  symmetric L18 P27 P46
  symmetric L18 P28 P44
  symmetric L18 P31 P43
  symmetric L18 P33 P39
  symmetric L18 P34 P42
  symmetric L18 P35 P41
  symmetric L18 P37 P40
  dimension "d121" distance L18 L19 = 10
  dimension "d122" distance L20 L22 = 5
  dimension "d123" distance P24 P25 = 1.8
  dimension "d125" distance L24 L26 = 11
  dimension "d126" distance L27 L28 = 1.3
  dimension "d127" angle L29 L30 = 45
  dimension "d128" angle L31 L32 = 45
  dimension "d129" distance L25 L27 = 4.5
work_plane "WorkPlane1" sketch "Sketch7"
extrude "Extrude11" sketch "Sketch7" profile of L20 L21 L22 L23 L24 L25 L26 L27 L28 L29 L31 L33 L34 L35 L36 L37 L38 L39 L40 L41 L42 L43 blind 25 second side blind 25
extrude "Extrude12" cut sketch "Sketch1" profile of C1 C2 C3 C4 to an object
offset_faces "OffsetFaces2" distance 0.1
sketch "Sketch5" plane through (0, 0, 32) normal (0, 0, 1) x axis (-1, 0, 0)
  line L1 (-6.45, 31.1397) -> (-4.7, 30.1294)
  line L2 (-6.45, 34.0265) -> (-6.45, 31.1397)
  line L3 (-4.7, 35.0369) -> (-6.45, 34.0265)
  line L4 (-4.7, 30.1294) -> (-4.7, 35.0369)
  line L5 (-4.7, 81.0369) -> (-6.45, 80.0265)
  line L6 (-4.7, 76.1294) -> (-4.7, 81.0369)
  line L7 (-6.45, 77.1397) -> (-4.7, 76.1294)
  line L8 (-6.45, 80.0265) -> (-6.45, 77.1397)
  line L9 (-48.7, 39.8566) -> (-48.7, 36.9699)
  line L10 (-46.2, 41.3) -> (-48.7, 39.8566)
  line L11 (-43.7, 39.8566) -> (-46.2, 41.3)
  line L12 (-43.7, 36.9699) -> (-43.7, 39.8566)
  line L13 (-46.2, 35.5265) -> (-43.7, 36.9699)
  line L14 (-48.7, 36.9699) -> (-46.2, 35.5265)
  line L15 (-22.7, 74.3566) -> (-22.7, 71.4699)
  line L16 (-20.2, 75.8) -> (-22.7, 74.3566)
  line L17 (-17.7, 74.3566) -> (-20.2, 75.8)
  line L18 (-17.7, 71.4699) -> (-17.7, 74.3566)
  line L19 (-20.2, 70.0265) -> (-17.7, 71.4699)
  line L20 (-22.7, 71.4699) -> (-20.2, 70.0265)
  line L21 (-29.2, 51.3566) -> (-29.2, 48.4699)
  line L22 (-26.7, 52.8) -> (-29.2, 51.3566)
  line L23 (-24.2, 51.3566) -> (-26.7, 52.8)
  line L24 (-24.2, 48.4699) -> (-24.2, 51.3566)
  line L25 (-26.7, 47.0265) -> (-24.2, 48.4699)
  line L26 (-29.2, 48.4699) -> (-26.7, 47.0265)
  line L27 (-45.45, 77.1397) -> (-42.95, 75.6964)
  line L28 (-45.45, 80.0265) -> (-45.45, 77.1397)
  line L29 (-42.95, 81.4699) -> (-45.45, 80.0265)
  line L30 (-40.45, 80.0265) -> (-42.95, 81.4699)
  line L31 (-40.45, 77.1397) -> (-40.45, 80.0265)
  line L32 (-42.95, 75.6964) -> (-40.45, 77.1397)
  line L33 (-38.95, 65.6397) -> (-36.45, 64.1964)
  line L34 (-38.95, 68.5265) -> (-38.95, 65.6397)
  line L35 (-36.45, 69.9699) -> (-38.95, 68.5265)
  line L36 (-33.95, 68.5265) -> (-36.45, 69.9699)
  line L37 (-33.95, 65.6397) -> (-33.95, 68.5265)
  line L38 (-36.45, 64.1964) -> (-33.95, 65.6397)
  line L39 (-51.95, 65.6397) -> (-49.45, 64.1964)
  line L40 (-51.95, 68.5265) -> (-51.95, 65.6397)
  line L41 (-49.45, 69.9699) -> (-51.95, 68.5265)
  line L42 (-46.95, 68.5265) -> (-49.45, 69.9699)
  line L43 (-46.95, 65.6397) -> (-46.95, 68.5265)
  line L44 (-49.45, 64.1964) -> (-46.95, 65.6397)
  line L45 (-48.7, 85.8566) -> (-48.7, 82.9699)
  line L46 (-46.2, 87.3) -> (-48.7, 85.8566)
  line L47 (-43.7, 85.8566) -> (-46.2, 87.3)
  line L48 (-43.7, 82.9699) -> (-43.7, 85.8566)
  line L49 (-46.2, 81.5265) -> (-43.7, 82.9699)
  line L50 (-48.7, 82.9699) -> (-46.2, 81.5265)
  line L51 (-32.45, 42.6397) -> (-29.95, 41.1964)
  line L52 (-32.45, 45.5265) -> (-32.45, 42.6397)
  line L53 (-29.95, 46.9699) -> (-32.45, 45.5265)
  line L54 (-27.45, 45.5265) -> (-29.95, 46.9699)
  line L55 (-27.45, 42.6397) -> (-27.45, 45.5265)
  line L56 (-29.95, 41.1964) -> (-27.45, 42.6397)
  line L57 (-22.7, 39.8566) -> (-22.7, 36.9699)
  line L58 (-20.2, 41.3) -> (-22.7, 39.8566)
  line L59 (-17.7, 39.8566) -> (-20.2, 41.3)
  line L60 (-17.7, 36.9699) -> (-17.7, 39.8566)
  line L61 (-20.2, 35.5265) -> (-17.7, 36.9699)
  line L62 (-22.7, 36.9699) -> (-20.2, 35.5265)
  line L63 (-16.2, 62.8566) -> (-16.2, 59.9699)
  line L64 (-13.7, 64.3) -> (-16.2, 62.8566)
  line L65 (-11.2, 62.8566) -> (-13.7, 64.3)
  line L66 (-11.2, 59.9699) -> (-11.2, 62.8566)
  line L67 (-13.7, 58.5265) -> (-11.2, 59.9699)
  line L68 (-16.2, 59.9699) -> (-13.7, 58.5265)
  line L69 (-29.2, 74.3566) -> (-29.2, 71.4699)
  line L70 (-26.7, 75.8) -> (-29.2, 74.3566)
  line L71 (-24.2, 74.3566) -> (-26.7, 75.8)
  line L72 (-24.2, 71.4699) -> (-24.2, 74.3566)
  line L73 (-26.7, 70.0265) -> (-24.2, 71.4699)
  line L74 (-29.2, 71.4699) -> (-26.7, 70.0265)
  line L75 (-7.2, 87.3) -> (-9.7, 85.8566)
  line L76 (-4.7, 85.8566) -> (-7.2, 87.3)
  line L77 (-4.7, 82.9699) -> (-4.7, 85.8566)
  line L78 (-7.2, 81.5265) -> (-4.7, 82.9699)
  line L79 (-9.7, 82.9699) -> (-7.2, 81.5265)
  line L80 (-9.7, 85.8566) -> (-9.7, 82.9699)
  line L81 (-19.45, 54.1397) -> (-16.95, 52.6964)
  line L82 (-19.45, 57.0265) -> (-19.45, 54.1397)
  line L83 (-16.95, 58.4699) -> (-19.45, 57.0265)
  line L84 (-14.45, 57.0265) -> (-16.95, 58.4699)
  line L85 (-14.45, 54.1397) -> (-14.45, 57.0265)
  line L86 (-16.95, 52.6964) -> (-14.45, 54.1397)
  line L87 (-16.2, 51.3566) -> (-16.2, 48.4699)
  line L88 (-13.7, 52.8) -> (-16.2, 51.3566)
  line L89 (-11.2, 51.3566) -> (-13.7, 52.8)
  line L90 (-11.2, 48.4699) -> (-11.2, 51.3566)
  line L91 (-13.7, 47.0265) -> (-11.2, 48.4699)
  line L92 (-16.2, 48.4699) -> (-13.7, 47.0265)
  line L93 (-9.7, 28.3566) -> (-9.7, 25.4699)
  line L94 (-7.2, 29.8) -> (-9.7, 28.3566)
  line L95 (-4.7, 28.3566) -> (-7.2, 29.8)
  line L96 (-4.7, 25.4699) -> (-4.7, 28.3566)
  line L97 (-7.2, 24.0265) -> (-4.7, 25.4699)
  line L98 (-9.7, 25.4699) -> (-7.2, 24.0265)
  line L99 (-55.2, 39.8566) -> (-55.2, 36.9699)
  line L100 (-52.7, 41.3) -> (-55.2, 39.8566)
  line L101 (-50.2, 39.8566) -> (-52.7, 41.3)
  line L102 (-50.2, 36.9699) -> (-50.2, 39.8566)
  line L103 (-52.7, 35.5265) -> (-50.2, 36.9699)
  line L104 (-55.2, 36.9699) -> (-52.7, 35.5265)
  line L105 (-32.45, 31.1397) -> (-29.95, 29.6964)
  line L106 (-32.45, 34.0265) -> (-32.45, 31.1397)
  line L107 (-29.95, 35.4699) -> (-32.45, 34.0265)
  line L108 (-27.45, 34.0265) -> (-29.95, 35.4699)
  line L109 (-27.45, 31.1397) -> (-27.45, 34.0265)
  line L110 (-29.95, 29.6964) -> (-27.45, 31.1397)
  line L111 (-48.7, 62.8566) -> (-48.7, 59.9699)
  line L112 (-46.2, 64.3) -> (-48.7, 62.8566)
  line L113 (-43.7, 62.8566) -> (-46.2, 64.3)
  line L114 (-43.7, 59.9699) -> (-43.7, 62.8566)
  line L115 (-46.2, 58.5265) -> (-43.7, 59.9699)
  line L116 (-48.7, 59.9699) -> (-46.2, 58.5265)
  line L117 (-45.45, 42.6397) -> (-42.95, 41.1964)
  line L118 (-45.45, 45.5265) -> (-45.45, 42.6397)
  line L119 (-42.95, 46.9699) -> (-45.45, 45.5265)
  line L120 (-40.45, 45.5265) -> (-42.95, 46.9699)
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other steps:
derived_base_feature "Derived Base Feature1" sketch "Sketch3" bodies "Body1", "Body2"
derived_base_feature "Derived Base Feature2" bodies "Power USB C"
derived_base_feature "Derived Base Feature3" bodies "Micro HDMI 2"
derived_base_feature "Derived Base Feature4" bodies "3.5 mm Audio"
derived_base_feature "Derived Base Feature5" bodies "Micro HDMI 1"
derived_base_feature "Derived Base Feature6" bodies "USB 2.0"
derived_base_feature "Derived Base Feature7" bodies "Display"
derived_base_feature "Derived Base Feature8" bodies "Processor"
derived_base_feature "Derived Base Feature9" bodies "Ethernet"
derived_base_feature "Derived Base Feature10" bodies "Kamera"
derived_base_feature "Derived Base Feature11" bodies "GPIO 40"
derived_base_feature "Derived Base Feature12" bodies "USB 3.0"
derived_base_feature "Derived Base Feature13" bodies "PoE"
create_component "CreateComponent1"
create_component "CreateComponent1"
create_component "CreateComponent2"
create_component "CreateComponent2"
named bodies: "Power USB C", "Micro HDMI 2", "3.5 mm Audio", "Micro HDMI 1", "USB 2.0", "Display", "Processor", "Ethernet", "Kamera", "GPIO 40", "USB 3.0", "PoE", "Body1", "Body2"

design "RPi_4_dummy_v2"
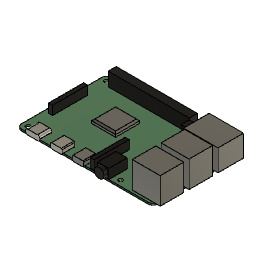
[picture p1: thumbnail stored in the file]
canvas "Ansichtsbereich"
sketch "Skizze4" plane through (0, 0, 0) normal (0, 0, 1) x axis (1, 0, 0)
  line L1 (52.4985, 25) -> (52.4985, -25)
  line L2 (-32.5, -25.0196) -> (-32.5, 24.5)
  line L3 (-29.5, 28) -> (49.4985, 28)
  line L4 (-32.5, 24.5) -> (-32.5, 25)
  line L5 (-29.5, -28) -> (49.4985, -28)
  line L6 (-32.5, -25.0196) -> (-32.5, -25)
  line L7 (29, -24.5) -> (-29, 24.5)
  line L8 (-29, -24.5) -> (29, 24.5)
  line L9 (-29, -24.5) -> (-29, 24.5)
  line L10 (29, -24.5) -> (-29, -24.5)
  line L11 (29, 24.5) -> (29, -24.5)
  line L12 (29, 24.5) -> (-29, 24.5)
  circle C1 centre (29, 24.5) radius 1.35
  circle C2 centre (29, -24.5) radius 1.35
  circle C3 centre (-29, -24.5) radius 1.35
  circle C4 centre (-29, 24.5) radius 1.35
  arc A1 centre (-29.5, 25) radius 3 clockwise from (-32.5, 25) to (-29.5, 28)
  arc A2 centre (-29.5, -25) radius 3 clockwise from (-29.5, -28) to (-32.5, -25)
  arc A3 centre (49.4985, -25) radius 3 clockwise from (52.4985, -25) to (49.4985, -28)
  arc A4 centre (49.4985, 25) radius 3 clockwise from (49.4985, 28) to (52.4985, 25)
  point P6 (-32.5, 28)
  point P4 (52.4985, 25)
  point P20 (52.4985, 25)
  point P10 (-29, 24.5)
  point P23 (-29, 24.5)
  point P8 (29, -24.5)
  point P24 (29, -24.5)
  point P7 (29, 24.5)
  point P25 (29, 24.5)
  point P9 (-29, -24.5)
  point P26 (-29, -24.5)
  point P27 (0, 0)
  point P1 (0, 0)
  point P3 (52.4985, -25)
  point P18 (52.4985, -25)
  point P28 (0, 0)
  point P29 (-29, 24.5)
  point P30 (-29, -24.5)
  point P31 (29, -24.5)
  point P32 (29, 24.5)
  point P33 (-29, 24.5)
  point P5 (-32.5, 24.5)
  parallel L1 L2
  horizontal L3
  vertical L4
  horizontal L5
  vertical L6
  coincident P6 L3
  coincident P6 L4
  tangent L3 A1
  tangent L4 A1
  tangent L5 A2
  tangent L6 A2
  tangent L5 A3
  equal A2 A3
  tangent L3 A4
  equal A2 A4
  equal A1 A2
  equal C2 C3
  equal C3 C4
  equal C1 C4
  coincident P4 P20
  coincident P10 P23
  coincident P8 P24
  coincident P7 P25
  coincident P9 P26
  midpoint L7 P27
  coincident P1 P27
  coincident P3 P18
  midpoint L8 P28
  coincident P1 P28
  vertical L1
  coincident P10 P29
  coincident P9 P30
  coincident P8 P31
  coincident P7 P32
  coincident P10 P33
  horizontal L12
  vertical L11
  tangent L1 A3
  tangent L1 A4
  dimension "d3" distance P4 P5 = 85
  dimension "d6" distance P5 P6 = 3.5
  dimension "d11" diameter C3 = 2.7
  dimension "d17" radius A1 = 3
  dimension "d57" distance P9 P10 = 49
  dimension "d58" distance P7 P10 = 58
  dimension "d61" distance L3 L5 = 56
  dimension "d62" distance L2 P10 = 3.5
  dimension "d63" distance L3 P10 = 3.5
extrude "Extrusion7" new body sketch "Skizze4" profile of L1 L2 L3 L4 L5 C1 C2 C3 C4 A1 A2 A3 A4 along normal blind 1
component_from_bodies "Körper->Berechn3"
